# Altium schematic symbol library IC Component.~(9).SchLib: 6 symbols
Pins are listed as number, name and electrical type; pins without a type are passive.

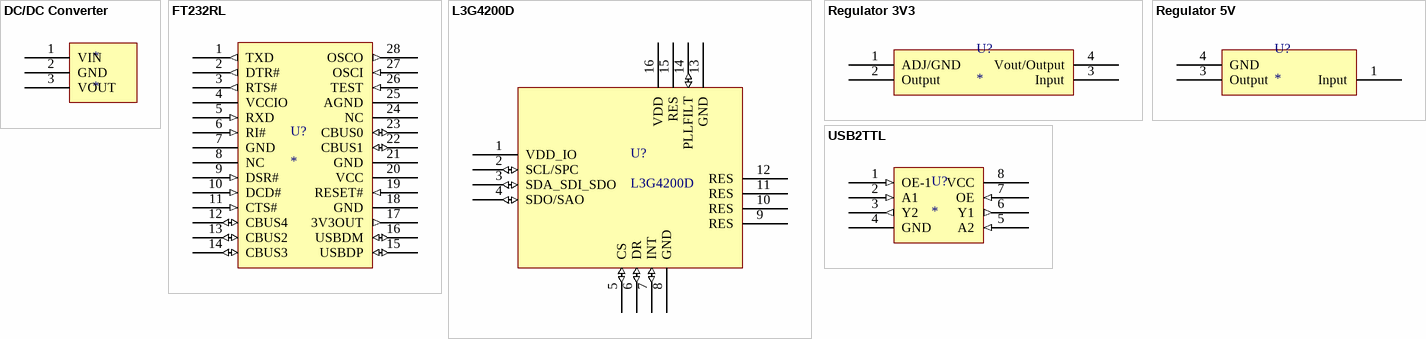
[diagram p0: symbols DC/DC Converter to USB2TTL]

## DC/DC Converter
designator *
footprint DC/DC Converter
pins: 1 VIN (power), 2 GND (power), 3 VOUT (power)

## FT232RL
designator U?
footprint USB TO SERIAL FT232RL SOP (SOP, 28-Leads, Body 10,25x5,40mm, Pitch 0,65mm, IPC Medium Density)
pins: 1 TXD (out), 2 DTR# (out), 3 RTS# (out), 4 VCCIO (power), 5 RXD (in), 6 RI# (in), 7 GND (power), 8 NC, 9 DSR# (in), 10 DCD# (in), 11 CTS# (in), 12 CBUS4 (io), 13 CBUS2 (io), 14 CBUS3 (io), 15 USBDP (io), 16 USBDM (io), 17 3V3OUT (out), 18 GND (power), 19 RESET# (in), 20 VCC (power), 21 GND (power), 22 CBUS1 (io), 23 CBUS0 (io), 24 NC, 25 AGND (power), 26 TEST (in), 27 OSCI (in), 28 OSCO (out)

## L3G4200D
designator U?
footprint L3G4200D (QFN, 16-Leads, Body 4,00x4,00mm, Pitch 0,65mm, Thermal Pad 2,03x2,03mm, IPC Medium Density)
pins: 1 VDD_IO (power), 2 SCL/SPC (io), 3 SDA_SDI_SDO (io), 4 SDO/SAO (io), 5 CS (io), 6 DR (io), 7 INT (io), 8 GND (power), 9 RES (power), 10 RES (power), 11 RES (power), 12 RES (power), 13 GND (power), 14 PLLFILT (io), 15 RES (power), 16 VDD (power)

## Regulator 3V3
designator U?
footprint Regulator 3V3 SOT230 (SOT223, 4-Leads, Body 6,50x7,00mm (avg), Pitch 2,30mm, IPC Medium Density)
pins: 1 ADJ/GND (power), 2 Output (power), 3 Input (power), 4 Vout/Output (power)

## Regulator 5V
designator U?
footprint Regulator 5V DPAK (D-PAK, 3-Pads, Body 6,20x6,66mm (max), IPC Medium Density)
pins: 1 Input (power), 3 Output (power), 4 GND (power)

## USB2TTL
designator U?
footprint USB2TTL TSSOP (TSSOP, 8-Leads, Body 2,05x2,35mm, Pitch 0,50mm, IPC Medium Density)
pins: 1 OE-1 (in), 2 A1 (in), 3 Y2 (out), 4 GND (power), 5 A2 (in), 6 Y1 (out), 7 OE (in), 8 VCC (power)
